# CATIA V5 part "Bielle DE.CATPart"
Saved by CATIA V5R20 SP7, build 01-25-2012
Part number: Bielle DE
Publications: "Point.1", "Point.2", "Droite.2", "Droite.3"
Bounding box of the stored display mesh (mm): x -10 to 10, y 0 to 0, z 0 to 450
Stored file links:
  U:\IAO\IAO\IAO\Bielle DE.CATPart
  U:\IAO\IAO\IAO\Squelette.CATProduct
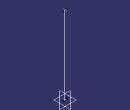
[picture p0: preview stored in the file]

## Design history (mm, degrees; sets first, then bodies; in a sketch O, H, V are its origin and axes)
External parameters (linked from other documents)
  `External.Longueur X4` = 450 mm
  `External.Longueur Demi Pivot` = 10 mm
Body1 (main body)
  Point1: (0, 0, 0)
  Line1: type PtDir, RefPoint Point1, Direction xy-plane, Start 0, End 450 {= `External.Longueur X4`}
  Point2: (0, 0, 0), relative to vertex of Line1
  Line2: type PtDir, RefPoint Point1, Direction yz-plane, Start -10, End 10 {= `External.Longueur Demi Pivot`}
  Line3: type PtDir, RefPoint Point2, Direction yz-plane, Start -10, End 10 {= `External.Longueur Demi Pivot`}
